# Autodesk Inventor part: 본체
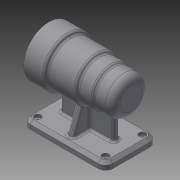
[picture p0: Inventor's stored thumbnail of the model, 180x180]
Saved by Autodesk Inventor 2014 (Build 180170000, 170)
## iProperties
Created: 2016-06
Part Number: 본체
Material: 일반
Document SubType Name: Modeling
Designer: USER
Density: 1 g/cm^3
Appearance: 기본값
Author: USER
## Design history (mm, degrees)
sketch "스케치1"
  geometry: L1 (0, 0)-(112, 0); L2 (0, 0)-(0, 25); L3 (0, 25)-(25, 25); L4 (25, 25)-(25, 27); L5 (25, 27)-(45, 27); L6 (45, 27)-(45, 30); L7 (45, 30)-(84, 30); L8 (84, 30)-(84, 34); L9 (84, 34)-(112, 34); L10 (112, 34)-(112, 0)
  constraints: 20 end point, 6 parallel, 3 perpendicular, 1 horizontal
  dimensions: "d0" = 112 distance of L1.start L1.end; "d2" = 50 diameter of L3 L1; "d3" = 54 diameter of L5 L1; "d4" = 60 diameter of L7 L1; "d5" = 68 diameter of L9 L1; "d6" = 25 distance of L2.end L3.end; "d7" = 45 distance between parallel lines of L6 L2; "d8" = 84 distance between parallel lines of L8 L2
revolve "회전1" sketch "스케치1" stored, may be unused: angle "d9" = 90 deg
fillet "모깎기1" dims "d10" = 3
fillet "모깎기2" dims "d11" = 3
fillet "모깎기3" dims "d12" = 10
sketch "스케치2"
  geometry: C1 r 34 at (0, 0) reference; 1 further point
  constraints: 1 coincident
hole "구멍1" sketch "스케치2" at (0, 0) diameter "d13" = 42; stored, may be unused: countersink angle "d17" = 90 deg, drill point angle "d19" = 0 deg; dims "d14" = 6, "d15" = 4, "d16" = 2, "d18" = 15
sketch "스케치3"
  geometry: C1 r 21 at (0, 0) reference; 1 further point
  constraints: 1 coincident
hole "구멍2" sketch "스케치3" at (0, 0) diameter "d20" = 48; stored, may be unused: countersink angle "d24" = 90 deg, drill point angle "d26" = 0 deg; dims "d21" = 6, "d22" = 4, "d23" = 2, "d25" = 54
sketch "스케치4"
  geometry: C1 r 24 at (0, 0) reference; 1 further point
  constraints: 1 coincident
hole "구멍3" sketch "스케치4" at (0, 0) diameter "d27" = 35; stored, may be unused: countersink angle "d31" = 90 deg, drill point angle "d33" = 0 deg; dims "d28" = 6, "d29" = 42, "d30" = 12, "d32" = 30
sketch "스케치5"
  geometry: C1 r 17.5 at (0, 0) reference; 1 further point
  constraints: 1 coincident
hole "구멍4" sketch "스케치5" at (0, 0) diameter "d34" = 21; stored, may be unused: countersink angle "d38" = 90 deg, drill point angle "d40" = 0 deg; dims "d35" = 6, "d36" = 32, "d37" = 4, "d39" = 7
chamfer "모따기1" distance "d41" = 1; stored, may be unused: second distance "d42" = 2, angle "d43" = 45 deg
fillet "모깎기6" dims "d46" = 0.3
fillet "모깎기7" dims "d47" = 3
node "작업 평면1"
sketch "스케치9"
  geometry: L1 (-112, 34)-(-112, -34) reference; L2 (0, 15)-(0, -15) reference; L3 (-112, 35)-(-112, -35); L4 (-112, -35)-(0, -35); L5 (0, -35)-(0, 35); L6 (0, 35)-(-112, 35); L7 (-112, 0)-(0, 0); 3 further points
  constraints: 10 end point, 4 midpoint, 2 perpendicular, 1 coincident, 1 collinear, 1 parallel, 1 vertical alignment
  dimensions: "d51" = 70 distance of L3.start L3.end; "d52" = 112 distance of L3.end L4.end; "d53" = 70 distance of L4.end L5.end
extrude "돌출1" join sketch "스케치9" distance "d54" = 10; taper "d55" = 0 deg
sketch "스케치10"
  geometry: L1 (-112, 35)-(-112, -35) reference; L2 (0, 35)-(-112, 35) reference; 2 further points
  dimensions: "d56" = 10 distance from line of L2 point (-102, 25); "d57" = 10 distance from line of L1 point (-102, 25)
hole "구멍5" sketch "스케치10" at (-102, 25) diameter "d58" = 5; stored, may be unused: countersink angle "d62" = 90 deg, drill point angle "d64" = 0 deg; dims "d59" = 6, "d60" = 9, "d61" = 4, "d63" = 7
fillet "모깎기8" dims "d71" = 10
chamfer "모따기2" distance "d72" = 4; stored, may be unused: second distance "d73" = 2, angle "d74" = 45 deg
sketch "스케치12"
  geometry: L1 (-102, 31)-(-10, 31) reference; L2 (-92, 4)-(-92, -4); L3 (-92, -4)-(-20, -4); L4 (-20, -4)-(-20, 4); L5 (-20, 4)-(-20, -4); L6 (-20, 4)-(-92, 4); L7 (-112, 25)-(-112, -25) reference; L8 (0, -25)-(0, 25) reference; 3 further points
  constraints: 10 end point, 2 midpoint, 2 parallel, 2 perpendicular, 1 horizontal alignment
  dimensions: "d79" = 8 distance of L2.start L2.end; "d80" = 8 distance of L4.end L3.end; "d81" = 20 distance between parallel lines of L7 L2; "d82" = 20 distance between parallel lines of L8 L4
extrude "돌출3" join sketch "스케치12" stored distance "d83" = 8; taper "d84" = 0 deg
node "작업 평면2"
sketch "스케치13"
  geometry: L1 (-10, 0)-(-10, 50) reference; L2 (-10, -3)-(-44.32, 9.491); L3 (-10, 53)-(-44.32, 40.509); L4 (-10, -4.5)-(-10, 4.5) reference; L5 (-10, 45.5)-(-10, 54.5) reference; L6 (-6, 60)-(0, 60) reference; L7 (0, -10)-(-6, -10) reference; A1 r 30 centre (-70, 25) between (-40.268, 29) and (-40.268, 21) reference; 4 further points
  constraints: 4 end point, 2 point on circle, 2 point on line, 4 other
  dimensions: "d85" = 7 distance from line of L6 L3.start; "d86" = 7 distance from line of L7 L2.start; "d87" = 110 deg angle of L4 L2; "d88" = 110 deg angle of L5 L3
  node "투영된 루프1"
feature "리브1" dims "d89" = 1, "d90" = 8, "d91" = 0, "d92" = 0, "d93" = 1, "d94" = 1
feature "리브2" dims "d95" = 1, "d96" = 8, "d97" = 0, "d98" = 0, "d99" = 1, "d100" = 1
fillet "모깎기9" dims "d101" = 3
fillet "모깎기10" dims "d102" = 3
sketch "스케치14" dims "d103" = 52
  geometry: C1 r 34 at (0, 0) reference; C2 r 22 at (0, 0) reference; 2 further points
  constraints: 2 horizontal alignment, 1 coincident, 2 other
hole "구멍6" sketch "스케치14" at (26, 0) diameter "d104" = 3.242; stored, may be unused: countersink angle "d108" = 90 deg, drill point angle "d110" = 118 deg; dims "d105" = 8, "d106" = 9, "d107" = 4, "d109" = 11
node "작업 평면3"
sketch "스케치15"
  geometry: L1 (47.5, -34)-(47.5, 34) reference; 2 further points
  constraints: 1 horizontal alignment, 1 other
  dimensions: "d114" = 48 distance from line of L1 point (-0.5, 0)
feature "엠보싱1" sketch "스케치15" dims "d0" = 112, "d2" = 50, "d3" = 54, "d4" = 60, "d5" = 68, "d6" = 25, "d7" = 45, "d8" = 84, "d115" = 0.5, "d116" = 0
node "솔리드1"
pattern_linear "직사각형 패턴1" dims "d67" = 92
pattern_circular "원형 패턴1" dims angle "d112" = 360 deg
